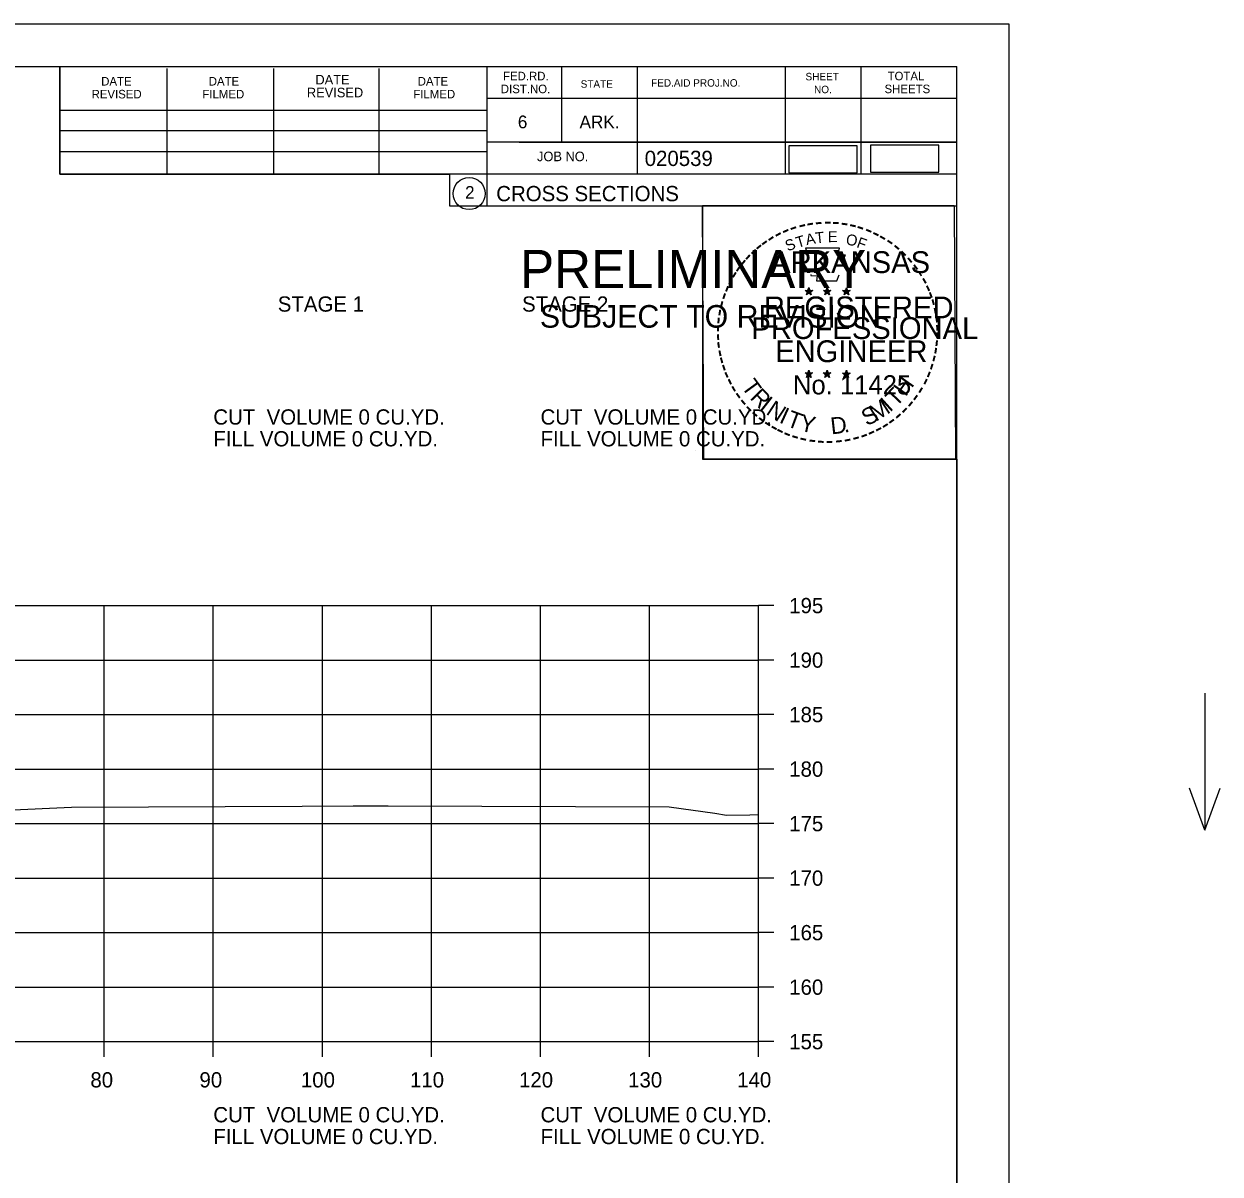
# Model space of a CAD drawing. Extents: x 915787 to 919910, y 133456 to 136717.
# Drawn here: x 916486.6 to 916596.3, y 136337.3 to 136442.8 of the extents above; entities that cross this region are included whole.
import ezdxf

# ---------------------------------------------------------------- set-up
doc = ezdxf.new("R2010")
doc.units = 0
for name, color, linetype in [('R_Axis', 7, 'Continuous'), ('R_Axis Annot', 7, 'Continuous'), ('R_Border', 7, 'Continuous'), ('R_Border Notes', 7, 'Continuous'), ('R_Border PE', 7, 'Continuous'), ('R_Border Prem', 7, 'Continuous'), ('R_Exist Surface', 7, 'Continuous'), ('R_Grid', 7, 'Continuous'), ('R_No Plot', 7, 'Continuous'), ('R_Water Annot', 7, 'Continuous'), ('R_Xsect Slope', 7, 'Continuous')]:
    doc.layers.add(name, color=color, linetype=linetype)

msp = doc.modelspace()

# ---------------------------------------------------------------- linework, layer by layer
at = {"layer": 'R_Axis'}
for p, q in [((916553.98, 136349.41), (916553.98, 136389.41)), ((916555.38, 136389.41), (916553.98, 136389.41)), ((916555.38, 136384.41), (916553.98, 136384.41)), ((916555.38, 136379.41), (916553.98, 136379.41)), ((916555.38, 136374.41), (916553.98, 136374.41)), ((916555.38, 136369.41), (916553.98, 136369.41)), ((916555.38, 136364.41), (916553.98, 136364.41)), ((916555.38, 136359.41), (916553.98, 136359.41)), ((916555.38, 136354.41), (916553.98, 136354.41)), ((916273.98, 136349.41), (916553.98, 136349.41)), ((916493.98, 136348.01), (916493.98, 136349.41)), ((916503.98, 136348.01), (916503.98, 136349.41)), ((916513.98, 136348.01), (916513.98, 136349.41)), ((916523.98, 136348.01), (916523.98, 136349.41)), ((916533.98, 136348.01), (916533.98, 136349.41)), ((916543.98, 136348.01), (916543.98, 136349.41)), ((916553.98, 136348.01), (916553.98, 136349.41)), ((916555.38, 136349.41), (916553.98, 136349.41))]:
    msp.add_line(p, q, dxfattribs=at)
at = {"layer": 'R_Border'}
for p, q in [((916255.98, 136438.87), (916572.16, 136438.87)), ((916489.9, 136428.99), (916489.9, 136438.87)), ((916499.76, 136428.99), (916499.76, 136438.67)), ((916509.52, 136428.99), (916509.52, 136438.67)), ((916519.2, 136428.99), (916519.2, 136438.67)), ((916529.06, 136438.87), (916529.06, 136426.07)), ((916535.9, 136438.87), (916535.9, 136431.93)), ((916542.84, 136438.87), (916542.84, 136428.99)), ((916556.42, 136438.87), (916556.42, 136428.99)), ((916563.36, 136438.87), (916563.36, 136428.99)), ((916572.16, 136233.41), (916572.16, 136438.87)), ((916572.16, 136435.93), (916529.06, 136435.93)), ((916572.16, 136435.95), (916572.16, 136435.95)), ((916489.9, 136434.85), (916529.06, 136434.85)), ((916489.9, 136432.99), (916529.06, 136432.99)), ((916572.16, 136431.93), (916529.06, 136431.93)), ((916532.02, 136431.93), (916572.16, 136431.93)), ((916489.9, 136428.99), (916489.9, 136431.05)), ((916489.9, 136431.05), (916529.06, 136431.05)), ((916572.16, 136428.99), (916489.9, 136428.99)), ((916529.06, 136426.07), (916572.16, 136426.07))]:
    msp.add_line(p, q, dxfattribs=at)
msp.add_circle((916527.44, 136427.2), 1.47, dxfattribs=at)
at = {"layer": 'R_Border PE'}
for p, q in [((916558.59, 136418.58), (916558.55, 136418.33)), ((916558.59, 136418.21), (916558.59, 136418.58)), ((916558.59, 136418.58), (916558.64, 136418.33)), ((916560.26, 136418.58), (916560.22, 136418.33)), ((916560.26, 136418.21), (916560.26, 136418.58)), ((916560.26, 136418.58), (916560.31, 136418.33)), ((916562.02, 136418.57), (916561.98, 136418.31)), ((916562.02, 136418.2), (916562.02, 136418.57)), ((916562.02, 136418.57), (916562.07, 136418.32)), ((916558.24, 136418.32), (916558.59, 136418.21)), ((916558.24, 136418.32), (916558.49, 136418.28)), ((916558.24, 136418.32), (916558.48, 136418.2)), ((916558.37, 136417.92), (916558.59, 136418.21)), ((916558.37, 136417.92), (916558.5, 136418.16)), ((916558.37, 136417.92), (916558.59, 136418.13)), ((916558.94, 136418.32), (916558.59, 136418.21)), ((916558.8, 136417.92), (916558.59, 136418.21)), ((916558.8, 136417.92), (916558.59, 136418.13)), ((916558.94, 136418.32), (916558.65, 136418.27)), ((916558.8, 136417.92), (916558.66, 136418.21)), ((916558.94, 136418.32), (916558.73, 136418.22)), ((916559.91, 136418.32), (916560.26, 136418.21)), ((916559.91, 136418.32), (916560.16, 136418.28)), ((916559.91, 136418.32), (916560.15, 136418.2)), ((916560.04, 136417.92), (916560.26, 136418.21)), ((916560.04, 136417.92), (916560.17, 136418.16)), ((916560.04, 136417.92), (916560.26, 136418.13)), ((916560.61, 136418.32), (916560.26, 136418.21)), ((916560.47, 136417.92), (916560.26, 136418.21)), ((916560.47, 136417.92), (916560.26, 136418.13)), ((916560.61, 136418.32), (916560.32, 136418.27)), ((916560.47, 136417.92), (916560.33, 136418.21)), ((916560.61, 136418.32), (916560.4, 136418.22)), ((916561.67, 136418.31), (916562.02, 136418.2)), ((916561.67, 136418.31), (916561.93, 136418.27)), ((916561.67, 136418.31), (916561.91, 136418.19)), ((916561.81, 136417.9), (916562.02, 136418.2)), ((916561.81, 136417.9), (916561.93, 136418.15)), ((916561.81, 136417.9), (916562.02, 136418.12)), ((916562.37, 136418.31), (916562.02, 136418.2)), ((916562.24, 136417.9), (916562.02, 136418.2)), ((916562.24, 136417.9), (916562.02, 136418.12)), ((916562.37, 136418.31), (916562.08, 136418.26)), ((916562.24, 136417.9), (916562.1, 136418.19)), ((916562.37, 136418.31), (916562.17, 136418.21)), ((916558.58, 136411), (916558.54, 136410.75)), ((916558.58, 136410.64), (916558.58, 136411)), ((916558.58, 136411), (916558.63, 136410.75)), ((916560.25, 136411), (916560.21, 136410.75)), ((916560.25, 136410.64), (916560.25, 136411)), ((916560.25, 136411), (916560.3, 136410.75)), ((916562.02, 136410.99), (916561.98, 136410.74)), ((916562.02, 136410.63), (916562.02, 136410.99)), ((916562.02, 136410.99), (916562.07, 136410.74)), ((916558.24, 136410.75), (916558.58, 136410.64)), ((916558.24, 136410.75), (916558.49, 136410.71)), ((916558.24, 136410.75), (916558.47, 136410.63)), ((916558.37, 136410.34), (916558.58, 136410.64)), ((916558.37, 136410.34), (916558.49, 136410.59)), ((916558.37, 136410.34), (916558.58, 136410.56)), ((916558.93, 136410.75), (916558.58, 136410.64)), ((916558.8, 136410.34), (916558.58, 136410.64)), ((916558.8, 136410.34), (916558.58, 136410.56)), ((916558.93, 136410.75), (916558.65, 136410.7)), ((916558.8, 136410.34), (916558.66, 136410.63)), ((916558.93, 136410.75), (916558.73, 136410.65)), ((916559.9, 136410.75), (916560.25, 136410.64)), ((916559.9, 136410.75), (916560.16, 136410.71)), ((916559.9, 136410.75), (916560.14, 136410.63)), ((916560.04, 136410.34), (916560.25, 136410.64)), ((916560.04, 136410.34), (916560.16, 136410.59)), ((916560.04, 136410.34), (916560.25, 136410.56)), ((916560.6, 136410.75), (916560.25, 136410.64)), ((916560.47, 136410.34), (916560.25, 136410.64)), ((916560.47, 136410.34), (916560.25, 136410.56)), ((916560.6, 136410.75), (916560.31, 136410.7)), ((916560.47, 136410.34), (916560.33, 136410.63)), ((916560.6, 136410.75), (916560.4, 136410.65)), ((916561.67, 136410.74), (916562.02, 136410.63)), ((916561.67, 136410.74), (916561.92, 136410.7)), ((916561.67, 136410.74), (916561.91, 136410.62)), ((916561.8, 136410.33), (916562.02, 136410.63)), ((916561.8, 136410.33), (916561.93, 136410.58)), ((916561.8, 136410.33), (916562.02, 136410.55)), ((916562.37, 136410.74), (916562.02, 136410.63)), ((916562.23, 136410.33), (916562.02, 136410.63)), ((916562.23, 136410.33), (916562.02, 136410.55)), ((916562.37, 136410.74), (916562.08, 136410.69)), ((916562.23, 136410.33), (916562.1, 136410.62)), ((916562.37, 136410.74), (916562.16, 136410.64))]:
    msp.add_line(p, q, dxfattribs=at)
for points in [[(916558.28, 136422.2), (916558.55, 136421.37)], [(916561.79, 136421.28), (916561.93, 136421.56), (916561.25, 136421.54), (916561.4, 136422.2), (916558.28, 136422.2)], [(916558.77, 136419.78), (916558.77, 136419.69), (916559.34, 136419.67), (916559.28, 136419.2), (916561.15, 136419.2), (916561.35, 136419.74)], [(916558.59, 136418.58), (916558.8, 136417.92), (916558.24, 136418.32), (916558.94, 136418.32), (916558.37, 136417.92), (916558.59, 136418.58)], [(916560.26, 136418.58), (916560.47, 136417.92), (916559.91, 136418.32), (916560.61, 136418.32), (916560.04, 136417.92), (916560.26, 136418.58)], [(916562.02, 136418.57), (916562.24, 136417.9), (916561.67, 136418.31), (916562.37, 136418.31), (916561.81, 136417.9), (916562.02, 136418.57)], [(916558.58, 136411), (916558.8, 136410.34), (916558.24, 136410.75), (916558.93, 136410.75), (916558.37, 136410.34), (916558.58, 136411)], [(916560.25, 136411), (916560.47, 136410.34), (916559.9, 136410.75), (916560.6, 136410.75), (916560.04, 136410.34), (916560.25, 136411)], [(916562.02, 136410.99), (916562.23, 136410.33), (916561.67, 136410.74), (916562.37, 136410.74), (916561.8, 136410.33), (916562.02, 136410.99)]]:
    msp.add_lwpolyline(points, dxfattribs=at)
for centre, radius in [((916558.59, 136418.21), 0.172), ((916558.59, 136418.21), 0.145), ((916558.59, 136418.21), 0.116), ((916558.59, 136418.21), 0.0991), ((916558.59, 136418.21), 0.0747), ((916558.59, 136418.21), 0.0495), ((916558.59, 136418.21), 0.0296), ((916560.26, 136418.21), 0.172), ((916560.26, 136418.21), 0.145), ((916560.26, 136418.21), 0.116), ((916560.26, 136418.21), 0.0991), ((916560.26, 136418.21), 0.0747), ((916560.26, 136418.21), 0.0495), ((916560.26, 136418.21), 0.0296), ((916562.02, 136418.2), 0.172), ((916562.02, 136418.2), 0.145), ((916562.02, 136418.2), 0.116), ((916562.02, 136418.2), 0.0991), ((916562.02, 136418.2), 0.0747), ((916562.02, 136418.2), 0.0495), ((916562.02, 136418.2), 0.0296), ((916558.58, 136410.64), 0.172), ((916558.58, 136410.64), 0.145), ((916560.25, 136410.64), 0.172), ((916560.25, 136410.64), 0.145), ((916562.02, 136410.63), 0.172), ((916562.02, 136410.63), 0.145), ((916558.58, 136410.64), 0.116), ((916558.58, 136410.64), 0.0991), ((916558.58, 136410.64), 0.0747), ((916558.58, 136410.64), 0.0495), ((916558.58, 136410.64), 0.0296), ((916560.25, 136410.64), 0.116), ((916560.25, 136410.64), 0.0991), ((916560.25, 136410.64), 0.0747), ((916560.25, 136410.64), 0.0495), ((916560.25, 136410.64), 0.0296), ((916562.02, 136410.63), 0.116), ((916562.02, 136410.63), 0.0991), ((916562.02, 136410.63), 0.0747), ((916562.02, 136410.63), 0.0495), ((916562.02, 136410.63), 0.0296)]:
    msp.add_circle(centre, radius, dxfattribs=at)
at = {"layer": 'R_Exist Surface'}
msp.add_lwpolyline([(916468.2, 136369.88), (916490.97, 136370.92), (916512.13, 136371.01), (916516.79, 136371.03), (916520.01, 136371.03), (916545.78, 136370.95), (916549.95, 136370.37), (916551.03, 136370.19), (916553.18, 136370.22), (916553.98, 136370.24)], dxfattribs=at)
at = {"layer": 'R_Grid'}
for p, q in [((916273.98, 136389.41), (916553.98, 136389.41)), ((916493.98, 136349.41), (916493.98, 136389.41)), ((916503.98, 136349.41), (916503.98, 136389.41)), ((916513.98, 136349.41), (916513.98, 136389.41)), ((916523.98, 136349.41), (916523.98, 136389.41)), ((916533.98, 136349.41), (916533.98, 136389.41)), ((916543.98, 136349.41), (916543.98, 136389.41)), ((916553.98, 136349.41), (916553.98, 136389.41)), ((916273.98, 136384.41), (916553.98, 136384.41)), ((916273.98, 136379.41), (916553.98, 136379.41)), ((916273.98, 136374.41), (916553.98, 136374.41)), ((916273.98, 136369.41), (916553.98, 136369.41)), ((916273.98, 136364.41), (916553.98, 136364.41)), ((916273.98, 136359.41), (916553.98, 136359.41)), ((916273.98, 136354.41), (916553.98, 136354.41)), ((916273.98, 136349.41), (916553.98, 136349.41))]:
    msp.add_line(p, q, dxfattribs=at)
at = {"layer": 'R_No Plot'}
for p, q in [((916243.57, 136442.76), (916576.91, 136442.76)), ((916548.19, 136403.61), (916548.19, 136403.61))]:
    msp.add_line(p, q, dxfattribs=at)
for points in [[(916243.57, 136442.76), (916576.91, 136442.76), (916576.91, 136229.43), (916243.57, 136229.43)], [(916489.9, 136438.87), (916489.9, 136428.99), (916525.63, 136428.99), (916525.63, 136426.07), (916548.83, 136426.07), (916548.83, 136402.85), (916572.16, 136402.85), (916572.16, 136233.41), (916255.98, 136233.41), (916255.98, 136438.87)], [(916548.83, 136426.1), (916571.92, 136426.1), (916572.04, 136402.85), (916548.94, 136402.85)]]:
    msp.add_lwpolyline(points, close=True, dxfattribs=at)
at = {"layer": 'R_Water Annot'}
for p, q in [((916594.88, 136381.39), (916594.88, 136368.82)), ((916594.88, 136368.82), (916593.48, 136372.67)), ((916594.88, 136368.82), (916596.28, 136372.67))]:
    msp.add_line(p, q, dxfattribs=at)
at = {"layer": 'R_Xsect Slope'}
for points in [[(916564.24, 136429.17), (916570.49, 136429.17), (916570.49, 136431.65), (916564.24, 136431.65)], [(916556.76, 136429.1), (916563.01, 136429.1), (916563.01, 136431.57), (916556.76, 136431.57)]]:
    msp.add_lwpolyline(points, close=True, dxfattribs=at)

# ---------------------------------------------------------------- texts
at = {"layer": 'R_Axis Annot'}
for s, p in [('195', (916556.78, 136388.71)), ('190', (916556.78, 136383.71)), ('185', (916556.78, 136378.71)), ('180', (916556.78, 136373.71)), ('175', (916556.78, 136368.71)), ('170', (916556.78, 136363.71)), ('165', (916556.78, 136358.71)), ('160', (916556.78, 136353.71)), ('155', (916556.78, 136348.71)), ('80', (916492.71, 136345.21)), ('90', (916502.71, 136345.21)), ('100', (916512.01, 136345.21)), ('110', (916522.01, 136345.21)), ('120', (916532.01, 136345.21)), ('130', (916542.01, 136345.21)), ('140', (916552.01, 136345.21))]:
    msp.add_text(s, height=1.4, dxfattribs=at).set_placement(p)
at = {"layer": 'R_Border'}
for s, height, p in [('FED.RD.', 0.782, (916530.54, 136437.59)), ('SHEET', 0.684, (916558.28, 136437.59)), ('TOTAL', 0.782, (916565.8, 136437.59)), ('DATE', 0.782, (916493.7, 136437.11)), ('DATE', 0.782, (916503.56, 136437.11)), ('DATE', 0.879, (916513.34, 136437.21)), ('DATE', 0.782, (916522.72, 136437.11)), ('DIST.NO.', 0.782, (916530.34, 136436.41)), ('STATE', 0.684, (916537.66, 136436.91)), ('FED.AID PROJ.NO.', 0.684, (916544.12, 136437.01)), ('NO.', 0.684, (916559.06, 136436.41)), ('SHEETS', 0.782, (916565.52, 136436.41)), ('REVISED', 0.782, (916492.82, 136435.93)), ('FILMED', 0.782, (916502.98, 136435.93)), ('REVISED', 0.879, (916512.56, 136436.03)), ('FILMED', 0.782, (916522.32, 136435.93)), ('6', 1.17, (916531.9, 136433.19)), ('ARK.', 1.172, (916537.56, 136433.19)), ('JOB NO.', 0.879, (916533.66, 136430.17)), ('020539', 1.4, (916543.53, 136429.73)), ('2', 1.17, (916527.06, 136426.72)), ('CROSS SECTIONS', 1.4, (916529.92, 136426.5))]:
    msp.add_text(s, height=height, rotation=360, dxfattribs=at).set_placement(p)
at = {"layer": 'R_Border Notes'}
for s, p in [('STAGE 1', (916509.89, 136416.37)), ('STAGE 2', (916532.29, 136416.37)), ('CUT  VOLUME 0 CU.YD.', (916503.98, 136406.01)), ('CUT  VOLUME 0 CU.YD.', (916533.98, 136406.01)), ('FILL VOLUME 0 CU.YD.', (916503.98, 136404.01)), ('FILL VOLUME 0 CU.YD.', (916533.98, 136404.01)), ('CUT  VOLUME 0 CU.YD.', (916503.98, 136342.01)), ('CUT  VOLUME 0 CU.YD.', (916533.98, 136342.01)), ('FILL VOLUME 0 CU.YD.', (916503.98, 136340.01)), ('FILL VOLUME 0 CU.YD.', (916533.98, 136340.01))]:
    msp.add_text(s, height=1.4, dxfattribs=at).set_placement(p)
at = {"layer": 'R_Border PE'}
for s, height, rotation, p in [('-', 1.6, 24.3072, (916556.39, 136423.06)), ('-', 1.6, 19.1761, (916557.03, 136423.33)), ('-', 1.6, 13.6301, (916557.78, 136423.57)), ('-', 1.6, 10.2193, (916558.46, 136423.73)), ('-', 1.6, 5.8968, (916559.19, 136423.84)), ('-', 1.6, 0.1862, (916559.96, 136423.91)), ('-', 1.6, 357.743, (916560.68, 136423.9)), ('-', 1.6, 352.1617, (916561.42, 136423.84)), ('-', 1.6, 347.2049, (916562.14, 136423.73)), ('-', 1.6, 342.3362, (916562.78, 136423.58)), ('-', 1.6, 337.8551, (916563.51, 136423.35)), ('-', 1.6, 36.2317, (916554.59, 136421.98)), ('-', 1.6, 34.0636, (916555.16, 136422.37)), ('-', 1.6, 28.7918, (916555.76, 136422.74)), ('S', 1, 21.594, (916556.64, 136421.88)), ('T', 1, 16.4036, (916557.55, 136422.21)), ('A', 1, 11.2132, (916558.38, 136422.46)), ('T', 1, 6.0228, (916559.22, 136422.63)), ('E', 1, 0.8323, (916560.33, 136422.74)), ('O', 1, 350.4515, (916561.93, 136422.53)), ('F', 1, 340.0707, (916562.89, 136422.3)), ('-', 1.6, 334.1211, (916564.14, 136423.08)), ('-', 1.6, 329.6409, (916564.72, 136422.8)), ('-', 1.6, 325.8627, (916565.37, 136422.44)), ('-', 1.6, 42.9622, (916553.68, 136421.18)), ('-', 1.6, 38.9507, (916554.11, 136421.6)), ('ARKANSAS', 2, 360, (916555.13, 136419.91)), ('-', 1.6, 320.5297, (916565.98, 136422.01)), ('-', 1.6, 315.5786, (916566.58, 136421.52)), ('-', 1.6, 50.6142, (916552.83, 136420.22)), ('-', 1.6, 48.423, (916553.23, 136420.7)), ('-', 1.6, 309.8797, (916567.14, 136420.97)), ('-', 1.6, 306.6522, (916567.67, 136420.37)), ('-', 1.6, 58.0706, (916552.09, 136419.12)), ('-', 1.6, 54.2325, (916552.41, 136419.65)), ('-', 1.4, 303.6753, (916568.16, 136419.8)), ('-', 1.6, 67.7743, (916551.52, 136417.9)), ('-', 1.6, 62.8713, (916551.78, 136418.51)), ('-', 1.6, 299.6684, (916568.47, 136419.2)), ('-', 1.6, 294.6628, (916568.8, 136418.58)), ('-', 1.6, 72.3945, (916551.3, 136417.27)), ('REGISTERED', 2, 360, (916554.46, 136415.76)), ('DWB', 0.01, 360, (916558.58, 136418.21)), ('DWB', 0.01, 360, (916560.25, 136418.21)), ('DWB', 0.01, 360, (916562.01, 136418.2)), ('-', 1.6, 290.5728, (916569.06, 136418.01)), ('-', 1.6, 285.1233, (916569.29, 136417.43)), ('-', 1.6, 81.2013, (916550.97, 136415.84)), ('-', 1.6, 75.461, (916551.1, 136416.56)), ('-', 1.6, 280.5493, (916569.49, 136416.69)), ('-', 1.6, 85.1863, (916550.89, 136415.15)), ('PROFESSIONAL', 2, 360, (916553.31, 136413.86)), ('-', 1.6, 276.5962, (916569.65, 136415.92)), ('-', 1.6, 274.3301, (916569.71, 136415.2)), ('-', 1.6, 94.1959, (916550.9, 136413.73)), ('-', 1.6, 89.0622, (916550.87, 136414.45)), ('-', 1.6, 269.9407, (916569.75, 136414.56)), ('-', 1.6, 98.9479, (916550.97, 136413.06)), ('ENGINEER', 2, 360, (916555.49, 136411.74)), ('-', 1.6, 260.9953, (916569.66, 136413.24)), ('-', 1.6, 263.5172, (916569.73, 136413.9)), ('-', 1.6, 101.7149, (916551.11, 136412.33)), ('-', 1.6, 105.4578, (916551.27, 136411.73)), ('-', 1.6, 255.7626, (916569.55, 136412.57)), ('-', 1.6, 109.0874, (916551.49, 136411.1)), ('-', 1.6, 114.0643, (916551.74, 136410.5)), ('-', 1.6, 247.8887, (916569.14, 136411.17)), ('-', 1.6, 252.8681, (916569.36, 136411.85)), ('-', 1.6, 115.7289, (916552.05, 136409.89)), ('T', 1.54, 306.0406, (916552.34, 136409.48)), ('No. 11425', 1.757, 360, (916557.12, 136408.78)), ('DWB', 0.01, 360, (916558.57, 136410.63)), ('DWB', 0.01, 360, (916560.24, 136410.64)), ('DWB', 0.01, 360, (916562.01, 136410.63)), ('H', 1.54, 54.6088, (916567.46, 136408.51)), ('-', 1.6, 244.6197, (916568.88, 136410.54)), ('-', 1.6, 120.4471, (916552.4, 136409.3)), ('-', 1.6, 125.8934, (916552.81, 136408.74)), ('R', 1.54, 314.005, (916553.11, 136408.43)), ('I', 1.54, 321.9694, (916554.01, 136407.5)), ('T', 1.54, 46.6444, (916566.58, 136407.57)), ('-', 1.6, 233.8452, (916568.08, 136409.14)), ('-', 1.6, 239.0712, (916568.49, 136409.79)), ('-', 1.6, 130.7181, (916553.27, 136408.19)), ('-', 1.6, 134.2238, (916553.78, 136407.64)), ('N', 1.54, 326.5002, (916554.57, 136407.03)), ('I', 1.54, 335.3603, (916555.78, 136406.24)), ('S', 1.54, 26.9312, (916563.89, 136405.84)), ('M', 1.54, 32.6563, (916564.73, 136406.25)), ('I', 1.54, 42.1136, (916566.01, 136407.09)), ('-', 1.6, 225.7653, (916567.17, 136408.01)), ('-', 1.6, 231.2538, (916567.65, 136408.57)), ('-', 1.6, 138.9338, (916554.31, 136407.18)), ('-', 1.6, 144.6463, (916554.87, 136406.77)), ('T', 1.54, 339.8912, (916556.44, 136405.91)), ('Y', 1.54, 347.8556, (916557.66, 136405.47)), ('D', 1.54, 6.3969, (916560.65, 136405.11)), ('-', 1.6, 215.7363, (916566.1, 136407.03)), ('-', 1.6, 221.0851, (916566.65, 136407.5)), ('-', 1.6, 148.0898, (916555.43, 136406.4)), ('-', 1.6, 151.5704, (916556.01, 136406.08)), ('-', 1.6, 154.6002, (916556.53, 136405.83)), ('-', 1.6, 158.5612, (916557.15, 136405.57)), ('.', 1.54, 13.7642, (916561.84, 136405.24)), ('-', 1.6, 204.2516, (916564.39, 136405.98)), ('-', 1.6, 207.3568, (916565.01, 136406.29)), ('-', 1.6, 212.2491, (916565.57, 136406.64)), ('-', 1.6, 162.7983, (916557.84, 136405.36)), ('-', 1.6, 167.5555, (916558.55, 136405.2)), ('-', 1.6, 173.1155, (916559.33, 136405.09)), ('-', 1.6, 176.5183, (916560.07, 136405.03)), ('-', 1.6, 181.5918, (916560.82, 136405.05)), ('-', 1.6, 185.8167, (916561.63, 136405.13)), ('-', 1.6, 191.2858, (916562.36, 136405.26)), ('-', 1.6, 195.4743, (916563.09, 136405.46)), ('-', 1.6, 200.7184, (916563.77, 136405.7))]:
    msp.add_text(s, height=height, rotation=rotation, dxfattribs=at).set_placement(p)
at = {"layer": 'R_Border Prem'}
for s, height, p in [('PRELIMINARY', 3.5, (916532.11, 136418.53)), ('DWB', 0.01, (916532.85, 136420.38)), ('SUBJECT TO REVISION', 2.0751, (916533.92, 136414.9))]:
    msp.add_text(s, height=height, rotation=360, dxfattribs=at).set_placement(p)

doc.saveas('drawing.dxf')
